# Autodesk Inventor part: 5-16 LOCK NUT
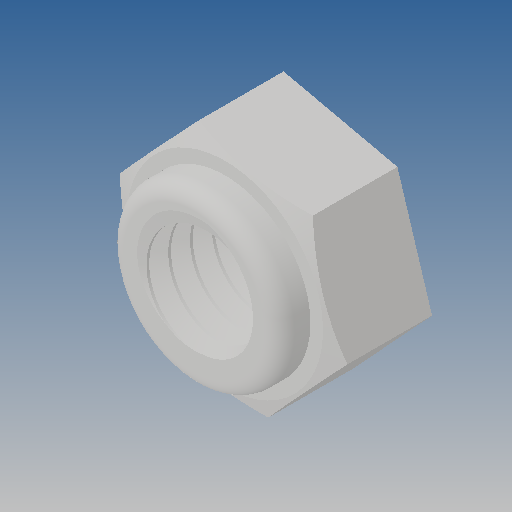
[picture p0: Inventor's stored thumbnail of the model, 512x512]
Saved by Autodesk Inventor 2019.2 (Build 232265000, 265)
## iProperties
Created: 2015-08
Part Number: 5-16 LOCK NUT
Material: Ogólny
Document SubType Name: Modeling
Designer: CADENGINEERING4
Density: 1 g/cm^3
Appearance: Domyślna
Author: CADENGINEERING4
Revision Number: ÈÎºÎ
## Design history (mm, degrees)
feature "ÇÐ³ý-Ðý×ª1"
node "Bryła1"
